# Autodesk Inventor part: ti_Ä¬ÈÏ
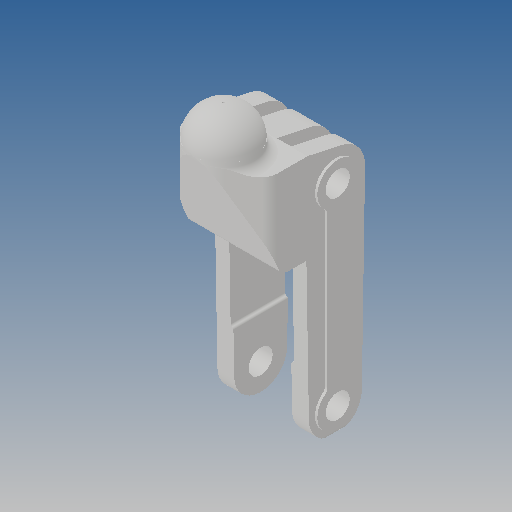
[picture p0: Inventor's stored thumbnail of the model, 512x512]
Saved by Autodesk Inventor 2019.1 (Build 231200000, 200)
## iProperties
Created: 2012-10
Part Number: ti_Ä¬ÈÏ
Material: Ogólny
Document SubType Name: Modeling
Designer: CADENGINEERING4
Density: 1 g/cm^3
Appearance: Domyślna
Author: CADENGINEERING4
Revision Number: ÈÎºÎ
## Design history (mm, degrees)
feature "NONE" [ÊäÈë]
feature "ÊäÈë2"
node "Bryła1"
node "Bryła2"
